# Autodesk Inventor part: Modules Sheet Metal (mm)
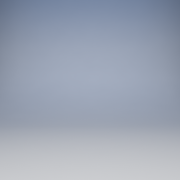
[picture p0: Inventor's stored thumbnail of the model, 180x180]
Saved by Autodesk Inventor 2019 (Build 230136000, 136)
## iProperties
Created: 2016-06
Part Number: Modules Sheet Metal (mm)
Material: Generic
Document SubType Name: Sheet Metal
Designer: Wally
Density: 1 g/cm^3
Sheet Metal Rule: Default
Appearance: Default
Author: Wally
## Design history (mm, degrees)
node "Sketch1"
other parameters: "Thickness" = 0.5, "BendRadius" = 0.5 (= Thickness), "BendReliefWidth" = 0.5 (= Thickness), "BendReliefDepth" = 0.25 (= 0.5 x Thickness), "CornerReliefSize" = 2 (= 4 x Thickness), "SeamGap" = 0.01, "MinimumRemnant" = 1 (= 2 x Thickness), "TransitionRadius" = 0.5 (= BendRadius), "JacobiRadiusSize" = 0.5 (= BendRadius), "GapSize" = 0.5 (= Thickness)
